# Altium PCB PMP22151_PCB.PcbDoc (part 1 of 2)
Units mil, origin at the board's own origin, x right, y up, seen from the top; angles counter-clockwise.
Board outline 3750 x 2000 mil, 2 copper layers (Top Layer, Bottom Layer), stack 62 mil thick; 80 components, 41 nets, 202 pads, 89 vias.
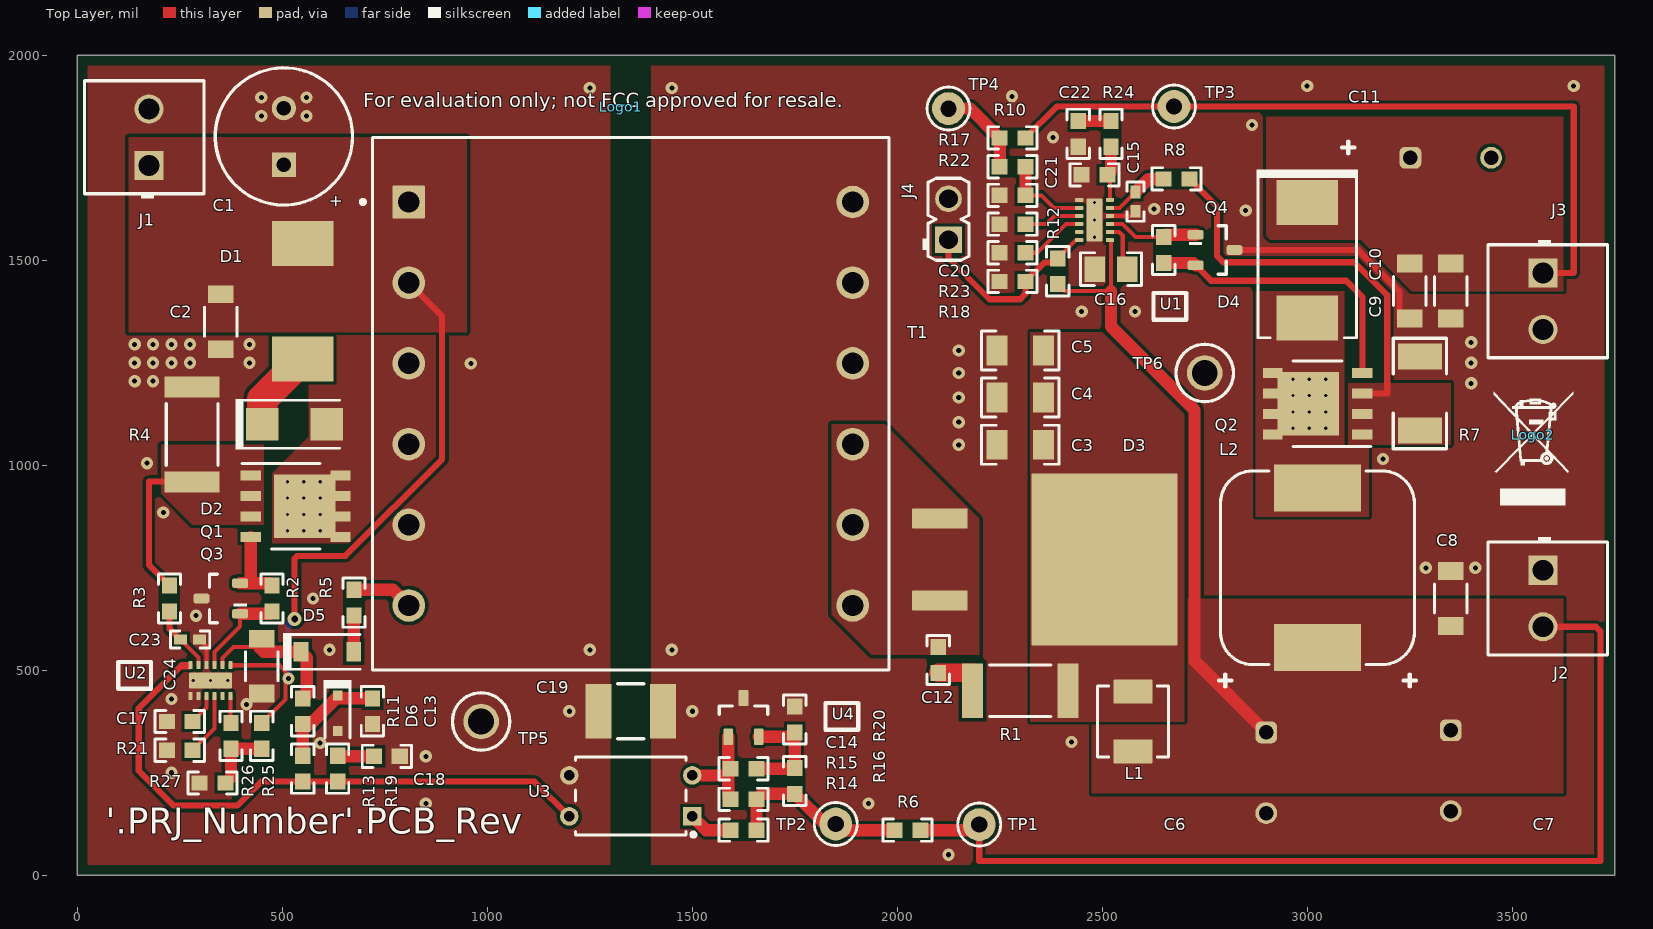
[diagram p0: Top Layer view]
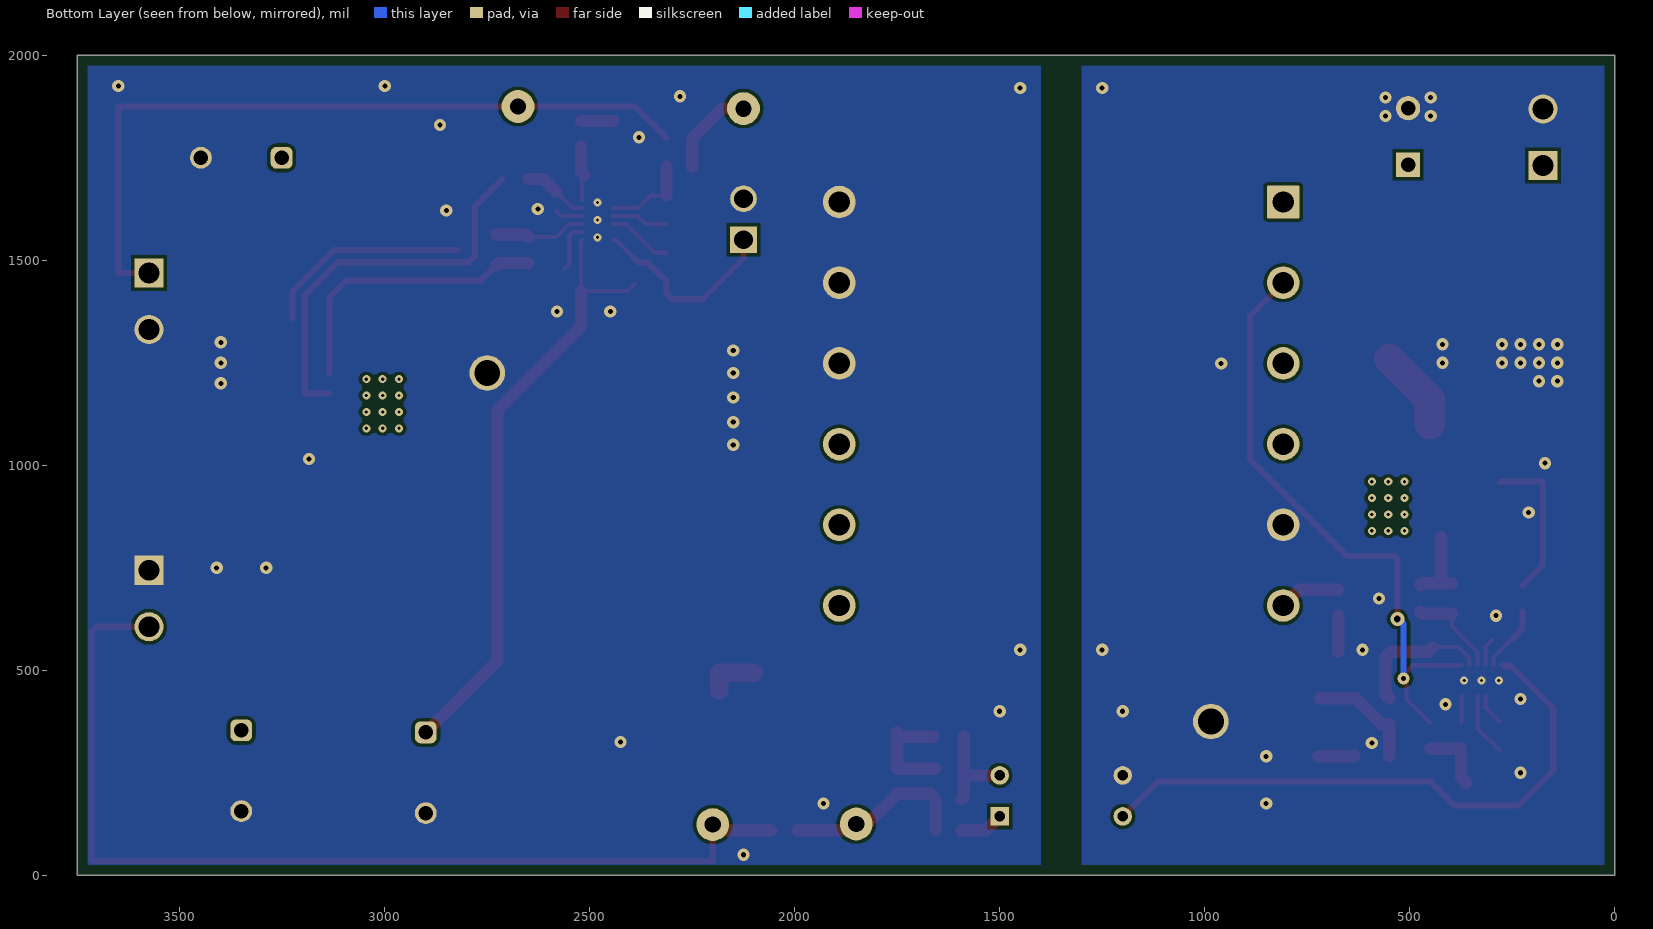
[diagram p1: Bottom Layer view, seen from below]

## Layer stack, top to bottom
Top Solder: solder mask 0.4, Solder Resist, Dk 3.5
Top Layer: signal copper 1.4
Dielectric1: core 59.2, FR-4, Dk 4.8
Bottom Layer: signal copper 1.4
Bottom Solder: solder mask 0.4, Solder Resist, Dk 3.5

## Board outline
0,0 3750,0 3750,2000 0,2000

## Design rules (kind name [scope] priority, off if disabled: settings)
AcuteAngle [All] p1: minimum=4.50000000000000E+0001 checktracksonly=FALSE
AssemblyTestPointUsage [All] p1: valid=2
BoardOutlineClearance BoardOutlineClearance_MountingHoles [OnCopper and InComponentClass('Mounting Holes')] p1: gap=25 ignorepadtopadclearanceinfootprint=FALSE
BoardOutlineClearance BoardOutlineClearance_Poly [OnCopper and InPoly] p2: gap=25 ignorepadtopadclearanceinfootprint=FALSE
BoardOutlineClearance [OnCopper and Not InComponentClass('Logo') and not InComponentClass('FiducialMark') and not InRegion(1000,500,4000,800)] p3: gap=25 ignorepadtopadclearanceinfootprint=FALSE
Clearance Clearance_Keepouts [((IsTrack Or IsArc) And Not InPoly) And IsFree and IsKeepOut vs ((IsTrack Or IsArc) And Not InPoly) And IsFree and IsKeepOut] p1: gap=0 ignorepadtopadclearanceinfootprint=FALSE
Clearance Clearance_Poly [InPolygon] p2: gap=8 ignorepadtopadclearanceinfootprint=FALSE except(0: Arc-Hole Track-Hole SMDPad-Hole THPad-Hole Via-Hole Fill-Hole Poly-Hole Region-Hole Text-Hole)
Clearance [All] p3: gap=7.87 ignorepadtopadclearanceinfootprint=FALSE except(0: Arc-Hole Track-Hole SMDPad-Hole THPad-Hole Via-Hole Fill-Hole Poly-Hole Region-Hole Text-Hole)
ComponentClearance ComponentClearance_MountingHoles_FiducialMarks [InComponentClass('Mounting Holes') vs InComponentClass('FiducialMark')] p1: gap=50 collisioncheckmode=3 verticalgap=10 showdistances=FALSE
ComponentClearance ComponentClearance_Shunt [InComponentClass('Header') vs InComponentClass('Shunt')] p2: gap=0 collisioncheckmode=3 verticalgap=0 showdistances=FALSE
ComponentClearance ComponentClearance_Logo [InComponentClass('Logo')] p3: gap=50 collisioncheckmode=3 verticalgap=10 showdistances=FALSE
ComponentClearance ComponentClearance_ScrewToNut [(HasFootprint('NY PMS 440 0025 PH')) vs (HasFootprint('Keystone_1902C'))] p4: gap=5 collisioncheckmode=3 verticalgap=10 showdistances=FALSE
ComponentClearance ComponentClearance_MountingHoles [InComponentClass('Mounting Holes')] p5: gap=250 collisioncheckmode=3 verticalgap=100000 showdistances=FALSE
ComponentClearance ComponentClearance_SmallPassives [HasFootprint('0201*') or HasFootprint('0402*') or HasFootprint('0508') or HasFootprint('0603*') or HasFootprint('0612') or HasFootprint('0805*') or HasFootprint('0815*') or HasFootprint('0830*') or HasFootprint('1206*') or HasFootprint('1210*') or HasFootprint('1808*') or HasFootprint('1812*') or HasFootprint('1825*') or HasFootprint('2010*') or HasFootprint('2220*') or HasFootprint('2225*') or HasFootprint('2512*') or HasFootprint('2728*') or HasFootprint('3518*') vs HasFootprint('0201*') or HasFootprint('0402*') or HasFootprint('0508') or HasFootprint('0603*') or HasFootprint('0612') or HasFootprint('0805*') or HasFootprint('0815*') or HasFootprint('0830*') or HasFootprint('1206*') or HasFootprint('1210*') or HasFootprint('1808*') or HasFootprint('1812*') or HasFootprint('1825*') or HasFootprint('2010*') or HasFootprint('2220*') or HasFootprint('2225*') or HasFootprint('2512*') or HasFootprint('2728*') or HasFootprint('3518*')] p6: gap=14.96 collisioncheckmode=3 verticalgap=10 showdistances=FALSE
ComponentClearance ComponentClearance_THtoSMT [IsThruComponent vs IsSMTComponent] p7: gap=15 collisioncheckmode=3 verticalgap=30 showdistances=FALSE
ComponentClearance ComponentClearance_THtoTH [IsThruComponent vs IsThruComponent] p8: gap=15 collisioncheckmode=3 verticalgap=30 showdistances=FALSE
ComponentClearance [All] p9: gap=15 collisioncheckmode=3 verticalgap=10 showdistances=FALSE
DiffPairsRouting [All] p1: maxlimit=100 minlimit=10 mostfreqgap=10 toplayer_minwidth=15 toplayer_maxwidth=15 toplayer_prefwidth=15 bottomlayer_minwidth=15 bottomlayer_maxwidth=15 bottomlayer_prefwidth=15 maxuncoupledlength=1000
FabricationTestPointUsage TestPointUsage [All] p1: valid=2 allowmultiple=FALSE
FabricationTestpoint Testpoint [All] p1: side=3 testpointundercomponent=TRUE minsize=40 maxsize=100 preferedsize=60 minholesize=0 maxholesize=40 preferedholesize=32 testpointgrid=1 allowsidetop=TRUE allowsidebottom=TRUE usegrid=TRUE gridtolerance=0.01
FanoutControl Fanout_LCC [IsLCC] p1: bgadir=Out bgaviamode=Centered fanoutstyle=Auto fanoutdirection=Alternating viagrid=1 // Fanout_LCC (Default Rule)
FanoutControl Fanout_BGA [IsBGA] p2: bgadir=Out bgaviamode=Centered fanoutstyle=Auto fanoutdirection=Alternating viagrid=1 // Fanout_BGA (Default Rule)
FanoutControl Fanout_Default [All] p4: bgadir=Out bgaviamode=Centered fanoutstyle=Auto fanoutdirection=Alternating viagrid=1 // Fanout_Default (Default Rule)
FanoutControl Fanout_Small [(CompPinCount < 5)] p5: bgadir=Out bgaviamode=Centered fanoutstyle=Auto fanoutdirection=OutThenIn viagrid=1 // Fanout_Small (Default Rule)
HoleSize [All] p1: absolutevalues=TRUE maxlimit=251 minlimit=7.87 maxpercent=80.000 minpercent=20.000
MinimumAnnularRing MinimumAnnularRing_ThermalPadVias [IsVia and InAnyComponent] p1: minimumring=5.91
MinimumAnnularRing [All] p2: minimumring=8
MinimumSolderMaskSliver MinimumSolderMaskSliver_Logo [InComponentClass('Logo') vs InComponentClass('Logo')] p1: minsoldermaskwidth=0.7
MinimumSolderMaskSliver [All] p2: minsoldermaskwidth=3.94
PlaneConnect [All] p1: planeconnectstyle=Direct reliefexpansion=10 reliefentries=4 reliefconductorwidth=10 reliefairgap=10
PolygonConnect [All] p1: connectstyle=Direct reliefconductorwidth=10 reliefentries=4 polygonreliefangle="90 Angle" airgapwidth=10
RoutingVias ThermalPadVias [IsVia and InAnyComponent] p1: holewidth=7.87 width=19.68 viastyle="Through Hole" minholewidth=7.87 minwidth=19.68 maxholewidth=12.99 maxwidth=23.62
RoutingVias [All] p2: holewidth=16 width=34 viastyle="Through Hole" minholewidth=7.87 minwidth=26 maxholewidth=40 maxwidth=65
SilkToBoardRegionClearance [Not ((IsComment or IsDesignator) And (Hide <> 'False')) and not InRegion(1000,500,4000,800)] p1:
SilkToSilkClearance SilkToSilkClearance_Pb-FreeLogo [(HasFootprint('Pb-Free_Overlay_Medium') OR HasFootprint('Pb-Free_Overlay_Small')) vs (HasFootprint('Pb-Free_Overlay_Medium') OR HasFootprint('Pb-Free_Overlay_Small'))] p1: silktosilkclearance=0
SilkToSilkClearance [All] p2: silktosilkclearance=4
SilkToSolderMaskClearance SilkToComponentPadClearance [IsPad and InAnycomponent] p1: minsilkscreentomaskgap=5 clearancetoexposedcopper=TRUE
SilkToSolderMaskClearance "Silk to Solder Mask Opening" [All] p2: minsilkscreentomaskgap=4 clearancetoexposedcopper=FALSE
SolderMaskExpansion [All] p1: expansion=1.97
Width [All] p1: maxlimit=100 minlimit=6 preferedwidth=10 checkconnectedcopper=TRUE
15 further rules are at their usual default settings.

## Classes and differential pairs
component class Header: J4

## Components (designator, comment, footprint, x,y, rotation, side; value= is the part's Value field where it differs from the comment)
C1 "50ZLJ100MT78X11.5" ZLJ_800X1150 504,1802 r90 top value=100uF
C2 "GRM31CR61H106KA12L" 1206_180 350,1350 r270 top value=10uF
C3 "GRM31MR71H105KA88L" 1206 2300,1050 r180 top value=1uF
C4 "GRM31MR71H105KA88L" 1206 2300,1165 r180 top value=1uF
C5 "GRM31MR71H105KA88L" 1206 2300,1280 r180 top value=1uF
C6 "860080675015" WCAP-ATLI_1000x1600 2900,250 r270 top value=220uF
C7 "860080675015" WCAP-ATLI_1000x1600 3350,255 r270 top value=220uF
C8 "GRM31CR71H475KA12L" 1206_180 3350,675 r90 top value=4.7uF
C9 "GRM31CR71H475KA12L" 1206_180 3350,1425 r270 top value=4.7uF
C10 "GRM31CR71H475KA12L" 1206_180 3250,1425 r270 top value=4.7uF
C11 "860080675015" WCAP-ATLI_1000x1600 3350,1750 r0 top value=220uF
C12 "GRM188R71H331KA01D" 0603 2100,525 r90 top value=330pF
C13 "GRM188R71E104KA01D" 0603 720,400 r90 top value=0.1uF
C14 "GRM188R71E153KA01D" 0603 1625,260 r180 top value=0.015uF
C15 "GRM1555C1E330JA01D" 0402 2581.3,1643.23 r270 top value=33pF
C16 "GRM219R71E105KA88D" 0805_HV 2521.3,1478.23 r180 top value=1uF
C17 "GRM188R71E104KA01D" 0603 250,375 r0 top value=0.1uF
C18 "GRM188R71E103KA01D" 0603 755,290 r180 top value=0.01uF
C19 "1812GC102KA1" 1812_254 1350,400 r180 top value=1000pF
C20 "GRM188R71E103KA01D" 0603 2281.3,1588.23 r180 top value=0.01uF
C21 "GRM188R71H821KA01D" 0603 2481.3,1708.23 r180 top value=820pF
C22 "GCM188R71E474KA64D" 0603 2441.3,1808.23 r270 top value=0.47uF
C23 "885012205055" 0402 275,575 r0 top value=100pF
C24 "C3216X7R1V106M160AC" 1206_190 450,510 r270 top value=10uF
D1 "SMCJ48CA-TR" SMC_Bi 550,1400 r270 top value=48V
D2 "MURA120T3G" SMA 530,1100 r0 top value=200V
D3 "MBRB20100CT-TP" DDPAK 2350,770 r0 top value=100V
D4 "B560C-13-F" SMC 3000,1500 r270 top value=60V
D5 "MMSD4148T1G" SOD-123 610,545 r0 top value=100V
D6 "MMSZ5231BS-7-F" SOD-323 635,395 r270 top value=5.1V
J1 "691214110002" Wurth_691214110002 175,1800 r90 top
J2 "691214110002" Wurth_691214110002 3575,675 r270 top
J3 "691214110002" Wurth_691214110002 3575,1400 r270 top
J4 "61300211121" WURTH_61300211121 2125,1600 r90 top
L1 "744373240010" WE-LHMI_4020 2575,375 r270 top value=100nH
L2 "7447709390" WE-PD_1210 3025,750 r90 top value=39uH
Logo1 "FCC disclaimer" FCC_disclaimer 1325,1875 r0 top
Logo2 "WEEE logo" WEEE_Minimum 3550,1075 r0 top
Q1 "SIR696DP-T1-GE3" PowerPAK_SO-8 532.5,900 r0 top value=200V
Q2 "SI7850DP-E3" PowerPAK_SO-8 3025,1150 r180 top value=60V
Q3 "MMBT3906" SOT-23 350,675 r180 top value="40 V"
Q4 "MMBT3906" SOT-23 2775,1525 r0 top value="40 V"
R1 "CRCW2512100RJNEG" 2512 2300,450 r0 top value=100
R2 "CRCW060310R0JNEA" 0603 475,675 r90 top value=10
R3 "CRCW06031K00FKEA" 0603 225,675 r90 top value=1.00k
R4 "ERJ-M1WSF8M0U" 2512 280,1075 r270 top value=0.008
R5 "CRCW060322R0JNEA" 0603 675,665 r90 top value=22
R6 "CRCW06030000Z0EA" 0603 2025,110 r0 top value=0
R7 "CSRN2010FK25L0" 2010 3275,1175 r270 top value=0.025
R8 "CRCW06031K00FKEA" 0603 2681.3,1698.23 r0 top value=1.00k
R9 "CRCW060310R0JNEA" 0603 2650,1525 r270 top value=10
R10 "CRCW06030000Z0EA" 0603 2281.3,1798.23 r0 top value=0
R11 "CRCW06032K49FKEA" 0603 550,400 r90 top value=2.49k
R12 "CRCW0603105KFKEA" 0603 2391.3,1473.23 r270 top value=105k
R13 "CRCW06032K49FKEA" 0603 550,260 r90 top value=2.49k
R14 "CRCW060310K0FKEA" 0603 1625,110 r0 top value=10.0k
R15 "CRCW060310K0FKEA" 0603 1625,185 r0 top value=10.0k
R16 "CRCW0603102KFKEA" 0603 1750,230 r270 top value=102k
R17 "CRCW0603100KFKEA" 0603 2281.3,1728.23 r180 top value=100k
R18 "CRCW060310K0FKEA" 0603 2281.3,1448.23 r0 top value=10.0k
R19 "CRCW0603499RFKEA" 0603 635,260 r270 top value=499
R20 "CRCW060310K0FKEA" 0603 1750,380 r270 top value=10.0k
R21 "CRCW0603215KFKEA" 0603 250,305 r180 top value=215k
R22 "CRCW06032K80FKEA" 0603 2281.3,1658.23 r0 top value=2.80k
R23 "CRCW060371K5FKEA" 0603 2281.3,1518.23 r0 top value=71.5k
R24 "CRCW060320K0FKEA" 0603 2521.3,1808.23 r270 top value=20.0k
R25 "CRCW0603105KFKEA" 0603 450,340 r90 top value=105k
R26 "CRCW060320K5FKEA" 0603 375,340 r90 top value=20.5k
R27 "CRCW060310K0FKEA" 0603 330,225 r0 top value=10.0k
T1 "750318773" FP-750318773_PTH_32MM0_33MM0-MFG 1350,1150 r0 top
TP1 "5000" Keystone5000 2200,123.74 r90 top
TP2 "5004" Keystone5004 1850,125 r90 top
TP3 "5000" Keystone5000 2675,1875 r90 top
TP4 "5004" Keystone5004 2125,1870 r90 top
TP5 "5011" Keystone5011 985,375 r0 top
TP6 "5011" Keystone5011 2750,1225 r0 top
U1 "LM5155DSST" DSS0012B 2481.3,1598.23 r180 top
U2 "LM5155DSST" DSS0012B 325,475 r270 top
U3 "VO618A-3" DIP-4 1350,193.43 r180 top
U4 "ATL431LIBIDBZR" DBZ0003A_N 1625,385 r90 top

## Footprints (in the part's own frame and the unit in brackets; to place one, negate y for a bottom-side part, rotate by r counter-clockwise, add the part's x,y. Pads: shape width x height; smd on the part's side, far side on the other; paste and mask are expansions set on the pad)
0402 [mm] "0402 from SM-752 data"
  rect 0.8x0.6 smd: 1(-0.6,0) 2(0.6,0)
  silkscreen extent -1.22,-0.52 1.22,0.52, body extent -0.55,-0.3 0.55,0.3, height 0.6
0603 [mm] "0603 from SM-752 data"
  rect 1x0.95 smd: 1(-0.8,0) 2(0.8,0)
  silkscreen extent -1.52,-0.69 1.52,0.69, body extent -0.87,-0.47 0.87,0.47, height 1
0805_HV [mil] "0805 with 30mil clearance between pads"
  rect 50x63 smd: 1(-40,0) 2(40,0)
  silkscreen extent -74,-40 74,40, body extent -43,-29 43,29, height 57
1206 [mm] "1206 from SM-752 data"
  rect 1.3x1.85 smd: 1(-1.45,0) 2(1.45,0)
  silkscreen extent -2.4,-1.21 2.4,1.21, body extent -1.7,-0.9 1.7,0.9, height 1.35
1206_180 [mm] "1206_180"
  rect 1.1x1.6 smd: 1(-1.7,0) 2(1.7,0)
  silkscreen extent -0.9,-1 0.9,1, body extent -1.75,-0.95 1.75,0.95, height 1.8
1206_190 [mm] "1206_190"
  rect 1.1x1.6 smd: 1(-1.7,0) 2(1.7,0)
  silkscreen extent -0.9,-1 0.9,1, body extent -1.75,-0.95 1.75,0.95, height 1.9
1812_254 [mm] "SMD, 2-Leads, Body 4.8x3.4mm"
  rect 1.6x3.4 smd: 1(-2,0) 2(2,0)
  silkscreen extent -0.8,-1.7 0.8,1.7, body extent -2.4,-1.7 2.4,1.7, height 2.54
2010 [mm] "Chip Capacitor, Body 5.08x2.54mm, IPC Medium Density"
  rect 1.6x2.7 smd: 1(-2.3,0) 2(2.3,0)
  silkscreen extent -3.42,-1.65 3.42,1.65, body extent -2.73,-1.45 2.73,1.45, height 1.66
2512 [mm] "Chip Resistor, Body 6.3x3.2mm, IPC Medium Density"
  rect 1.3x3.4 smd: 1(-2.95,0) 2(2.95,0)
  silkscreen extent -1.9,-1.6 1.9,1.6, body extent -3.22,-1.67 3.22,1.67, height 0.71
DBZ0003A_N [mm] "SOT23, 3-Leads, Body 2.9x1.3mm, Pitch 0.95mm, Lead Span 2.4mm, IPC Medium Density"
  rrect17% 1x0.6 smd: 1(-1.2,0.95) 2(-1.2,-0.95) 3(1.2,0)
  silkscreen extent 0.2,-1.5 0.7,1.5, body extent -1.26,-1.46 1.26,1.46, height 0.98
DDPAK [mil] "D2-PAK, 3-Pads, Body 9.7x10.4mm (max), TO-263AB, using Vishay Silionix recommended pad sizes"
  rrect8% 135x49.49 smd: 1(-246.06,100) 3(-246.06,-100)
  rrect1% 355x420 smd paste-181.1: 2(155.51,0)
  body extent -295,-202 324,202, height 180
DIP-4 [mm] "DIP, 4-Leads, Body 6.86x4.83mm, Pitch 2.54mm"
  rect 1.15x1.15 hole 0.65: 1(-3.81,1.27)
  round 1.15 hole 0.65: 2(-3.81,-1.27) 3(3.81,-1.27) 4(3.81,1.27)
  silkscreen extent -4,-2.41 3.43,2.52, body extent -4.02,-2.41 4.02,2.41, height 5.59
DSS0012B [mm] "WSON-10"
  rrect40% 0.5x0.25 smd: 1(-0.95,1.25) 2(-0.95,0.75) 3(-0.95,0.25) 4(-0.95,-0.25) 5(-0.95,-0.75) 6(-0.95,-1.25) 7(0.95,-1.25) 8(0.95,-0.75) 9(0.95,-0.25) 10(0.95,0.25) 11(0.95,0.75) 12(0.95,1.25)
  rrect11% 1x2.65 smd paste-0.5: 13(0,0)
  body extent -1,-1.5 1,1.5, height 0.81
FCC_disclaimer [mil]
FP-750318773_PTH_32MM0_33MM0-MFG [mm]
  rrect5% 2.02x2.02 hole 1.32 paste-1000 mask+0: 1(-13.75,12.5)
  round 2.02 hole 1.32 paste-1000 mask+0: 2(-13.75,7.5) 3(-13.75,2.5) 4(-13.75,-2.5) 5(-13.75,-7.5) 6(-13.75,-12.5) 7(13.75,-12.5) 8(13.75,-7.5) 9(13.75,-2.5) 10(13.75,2.5) 11(13.75,7.5) 12(13.75,12.5)
  silkscreen extent -16.72,-16.5 16,16.5, body extent -16.1,-16.6 16.1,16.6, height 0.25
Keystone5000 [mil] "For Keystone 500x miniature loop terminals"
  round 80 hole 40: 1(0,0)
  silkscreen extent -52,-52 52,52, body extent -49,-49 49,49, height 182
Keystone5004 [mil] "For Keystone 500x miniature loop terminals"
  round 80 hole 40: 1(0,0)
  silkscreen extent -52,-52 52,52, body extent -49,-49 49,49, height 182
Keystone5011 [mil] "Keystone Multipurpose loops"
  round 87 hole 63: 1(0,0)
  silkscreen extent -70,-70 70,70, body extent -63,-63 63,62, height 319
PowerPAK_SO-8 [mil] "Vishay PowerPAK SO-8, Body 5.3x6.0mm (max), Pitch 1.27mm, IPC Medium Density"
  rect 50x24 smd mask+2.99: 1(-109.5,75) 2(-109.5,25) 3(-109.5,-25) 4(-109.5,-75)
  rect 48x24 smd mask+2.99: 5(109.5,-75) 8(109.5,75)
  rect 48x24 smd paste-12 mask+2.99: 6(109.5,-25) 7(109.5,25)
  rect 150x154 smd paste-75 mask+2.99: 9(22.5,0)
  silkscreen extent -130,-104 59,104, body extent -121,-102 121,102, height 43
SMA [mm] "Molded Diode, 2-Leads, Body 4.3x2.6mm, IPC Medium Density, based on OnSemi component dimensions and land pattern"
  rect 2x2 smd: 1(-2,0) 2(2,0)
  silkscreen extent -3.66,-1.57 2.79,1.57, body extent -2.6,-1.3 2.6,1.3, height 2.42
SMC [mil] "Molded Diode, 2-Leads, Body 6.9x5.8mm, IPC Medium Density, based on OnSemi component dimensions and land patterns"
  rect 110x150 smd: 1(-140.49,0) 2(140.49,0)
  silkscreen extent -221,-123 189,124, body extent -156,-116 156,116, height 91
SMC_Bi [mil] "SMC, no polarity mark"
  rect 110x150 smd: 1(-140.49,0) 2(140.49,0)
  body extent -156,-116 156,116, height 92
SOD-123 [mm] "On Semi recommended land pattern"
  rect 0.915x1.22 smd: 1(-1.637,0) 2(1.637,0)
  silkscreen extent -2.74,-1.17 2.03,1.17, body extent -1.93,-0.9 1.93,0.9, height 1.35
SOD-323 [mm] "NXP recommended land pattern"
  rect 0.6x0.6 smd paste-0.05: 1(-1.1,0) 2(1.1,0)
  silkscreen extent -2.06,-0.86 1.53,0.86, body extent -1.3,-0.67 1.3,0.68, height 1.1
SOT-23 [mm] "SOT23, 3-Leads, Body 2.9x1.3mm, Pitch 0.95mm, Lead Span 2.5mm, IPC Medium Density"
  rrect50% 1x0.6 smd: 1(-1.2,0.95) 2(-1.2,-0.95) 3(1.2,0)
  silkscreen extent -1.62,-1.5 0.7,1.5, body extent -1.16,-1.45 1.21,1.45, height 1
WCAP-ATLI_1000x1600 [mm] "TH, 2-Leads, Dia 10mm, Pin Spacing 5mm"
  rrect50% 1.35x1.35 hole 0.9: 1(-2.5,0)
  round 1.35 hole 0.9: 2(2.5,0)
  body extent -5.25,-5.25 5.26,5.25, height 17.51
WE-LHMI_4020 [mm] "WERTH"
  rrect7% 1.5x2.4 smd: 1(-1.85,0) 2(1.85,0)
  silkscreen extent -2.2,-2.2 2.2,2.2, body extent -2.15,-2.15 2.15,2.15, height 2
WE-PD_1210 [mm] "Wurth Elektronik recommended land pattern"
  rect 2.9x5.4 smd: 1(-4.95,0) 2(4.95,0)
  silkscreen extent -6,-6 6,6, body extent -6,-6 6,6, height 10.01
WEEE_Minimum [mil] "WEEElie bin"
  silkscreen extent -95,-172 99,104
WURTH_61300211121 [mm] "Header, 2.54mm, 2x1, TH"
  rect 1.65x1.65 hole 1.15: 1(-1.27,0)
  round 1.65 hole 1.15: 2(1.27,0)
  silkscreen extent -2.54,-1.27 2.54,1.6, body extent -2.54,-1.27 2.54,1.27, height 8.54
Wurth_691214110002 [mm] "Receptacle, 3.5mm, 2x1, TH"
  rect 1.8x1.8 hole 1.3: 1(-1.75,0)
  round 1.8 hole 1.3: 2(1.75,0)
  silkscreen extent -3.8,-3.4 3.5,4, body extent -3.9,-3.4 3.5,4, height 8.5
ZLJ_800X1150 [mm] "Rubycon"
  rect 1.5x1.5 hole 0.889: 1(-1.75,0)
  round 1.5 hole 0.889: 2(1.75,0)
  silkscreen extent -4.25,-4.25 4.25,4.25, body extent -4.22,-4.24 4.24,4.24, height 13.01

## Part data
C1: library part CMP-0009787-2, "CAP, AL, 100 uF, 50 V, +/- 20%, 0.12 ohm, TH", Cap_Case=8x11.5, Manufacturer=Rubycon, Supplier Part Number 1=1189-1662-1-ND, Tolerance_%=20%, Value1="0.12 ohm", Value2=50V, ValueDisplayed=100uF
C2: library part CMP-0008954-2, "CAP, CERM, 10 uF, 50 V, +/- 10%, X5R, 1206", Cap_Case=1206, Manufacturer=MuRata, Supplier Part Number 1=490-5961-1-ND, TempCo=X5R, Tolerance_%=10%, Value1=Unknown, Value2=50V, ValueDisplayed=10uF
C3 C4 C5: library part CMP-0008992-2, "CAP, CERM, 1 uF, 50 V, +/- 10%, X7R, 1206", Cap_Case=1206, Manufacturer=MuRata, Supplier Part Number 1=GRM31MR71H105KA88L-ND, TempCo=X7R, Tolerance_%=10%, Value1=Unknown, Value2=50V, ValueDisplayed=1uF
C6 C7 C11: library part CMP-0081643-1, "CAP, AL, 220 µF, 50 V, +/- 20%, TH", Cap_Case=10x16mm, Manufacturer="Wurth Elektronik", Supplier Part Number 1=732-9057-1-ND, Tolerance_%=20%, Value2=50V, ValueDisplayed=220µF
C8 C9 C10: library part CMP-0008969-2, "CAP, CERM, 4.7 uF, 50 V, +/- 10%, X7R, 1206", Cap_Case=2220, Manufacturer=MuRata, Supplier Part Number 1=24R6347, TempCo=X7R, Tolerance_%=10%, Value1=Unknown, Value2=50V, ValueDisplayed=4.7uF
C12: library part CMP-0007449-4, "CAP, CERM, 330 pF, 50 V, +/- 10%, X7R, 0603", Cap_Case=0603, Manufacturer=MuRata, Supplier Part Number 1=490-1486-1-ND, TempCo=X7R, Tolerance_%=10%, Value1=Unknown, Value2=50V, ValueDisplayed=330pF
C13 C17: library part CMP-0007404-4, "CAP, CERM, 0.1 uF, 25 V, +/- 10%, X7R, 0603", Cap_Case=0603, Manufacturer=MuRata, Supplier Part Number 1=490-1524-1-ND, TempCo=X7R, Tolerance_%=10%, Value1=Unknown, Value2=25V, ValueDisplayed=0.1uF
C14: library part CMP-0007410-5, "CAP, CERM, 0.015 uF, 25 V, +/- 10%, X7R, 0603", Cap_Case=0603, Manufacturer=MuRata, Supplier Part Number 1=81-GRM39X153K25D, TempCo=X7R, Tolerance_%=10%, Value1=Unknown, Value2=25V, ValueDisplayed=0.015uF
C15: library part CMP-0006377-2, "CAP, CERM, 33 pF, 25 V, +/- 5%, C0G/NP0, 0402", Cap_Case=0402, Manufacturer=MuRata, Supplier Part Number 1=81-GRM1555C1E330JA1D, TempCo=C0G/NP0, Tolerance_%=5%, Value1=Unknown, Value2=25V, ValueDisplayed=33pF
C16: library part CMP-0008217-2, "CAP, CERM, 1 uF, 25 V, +/- 10%, X7R, 0805", Cap_Case=0805, Manufacturer=MuRata, Supplier Part Number 1=GRM219R71E105KA88D-ND, TempCo=X7R, Tolerance_%=10%, Value1=Unknown, Value2=25V, ValueDisplayed=1uF
C18 C20: library part CMP-0007403-4, "CAP, CERM, 0.01 uF, 25 V, +/- 10%, X7R, 0603", Cap_Case=0603, Manufacturer=MuRata, Supplier Part Number 1=490-1520-1-ND, TempCo=X7R, Tolerance_%=10%, Value1=Unknown, Value2=25V, ValueDisplayed=0.01uF
C19: library part CMP-0009293-2, "CAP, CERM, 1000 pF, 2000 V, +/- 10%, X7R, 1812", Cap_Case=1812, Manufacturer=AVX, Supplier Part Number 1=581-1812GC102KA11A, TempCo=X7R, Tolerance_%=10%, Value1=Unknown, Value2=2000V, ValueDisplayed=1000pF
C21: library part CMP-0007464-4, "CAP, CERM, 820 pF, 50 V, +/- 10%, X7R, 0603", Cap_Case=0603, Manufacturer=MuRata, Supplier Part Number 1=490-1493-1-ND, TempCo=X7R, Tolerance_%=10%, Value1=Unknown, Value2=50V, ValueDisplayed=820pF
C22: library part CMP-0007142-4, "CAP, CERM, 0.47 uF, 25 V, +/- 10%, X7R, AEC-Q200 Grade 1, 0603", Cap_Case=0603, Manufacturer=MuRata, Supplier Part Number 1=490-4776-1-ND, TempCo=X7R, Tolerance_%=10%, Value1=Unknown, Value2=25V, ValueDisplayed=0.47uF
C23: library part CMP-0006230-2, "CAP, CERM, 100 pF, 50 V, +/- 10%, X7R, 0402", Cap_Case=0402, Manufacturer="Wurth Elektronik", Supplier Part Number 1=732-7550-1-ND, TempCo=X7R, Tolerance_%=10%, Value1=Unknown, Value2=50V, ValueDisplayed=100pF
C24: library part CMP-0008706-2, "CAP, CERM, 10 uF, 35 V, +/- 20%, X7R, 1206_190", Cap_Case=1206, Manufacturer=TDK, Supplier Part Number 1=445-8034-1-ND, TempCo=X7R, Tolerance_%=20%, Value1=Unknown, Value2=35V, ValueDisplayed=10uF
D1: library part CMP-0085460-1, "Diode, TVS, Bi, 48 V, 77.4 Vc, 1500 W, 20 A, SMC (No Polarity Mark)", Manufacturer=STMicroelectronics, Value1=77.4V
D2: library part CMP-0029038-2, "Diode, Ultrafast, 200 V, 1 A, SMA", Manufacturer="ON Semiconductor", Value1=1A, Value2=0.0875V
D3: library part CMP-0076915-3, "Diode, Schottky, 100 V, 20 A, DDPAK", Manufacturer="Micro Commercial Components", Value1=20A, Value2=0.85V
D4: library part CMP-0028433-2, "Diode, Schottky, 60 V, 5 A, SMC", Manufacturer="Diodes Inc.", Value1=5A, Value2=0.7V
D5: library part CMP-0029032-2, "Diode, Switching, 100 V, 0.2 A, SOD-123", Manufacturer="ON Semiconductor", Value1=0.2A, Value2=1V
D6: library part CMP-0005854-3, "Diode, Zener, 5.1 V, 200 mW, SOD-323", Manufacturer="Diodes Inc.", Power_W=200mW, Value1=0.2W
J1 J2 J3: library part CMP-0054825-2, "Terminal Block, 3.5mm, 2x1, Tin, TH", Color=Green, Current_A=10A, Manufacturer="Wurth Elektronik", Supplier Part Number 1=732-2747-ND, Voltage_V=300V
J4: library part CMP-0054794-1, "Header, 2.54 mm, 2x1, Gold, TH", Manufacturer="Wurth Elektronik", Supplier Part Number 1=732-5315-ND
L1: library part CMP-0064065-1, "Inductor, Shielded Drum Core, Powdered Iron, 100 nH, 12 A, 0.0032 ohm, SMD", Manufacturer="Wurth Elektronik", Supplier Part Number 1=732-3344-1-ND, Value1="0.0032 ohm", Value2=12A, ValueDisplayed=100nH
L2: library part CMP-0064541-2, "Inductor, Shielded Drum Core, Metal Composite, 39 uH, 4.1 A, 0.0439 ohm, SMD", Manufacturer="Wurth Elektronik", Supplier Part Number 1=732-1245-1-ND, Value1="0.0439 ohm", Value2=4.1A, ValueDisplayed=39uH
Logo1: library part CMP-0074847-1, "FCC_disclaimer"
Logo2: library part CMP-0074769-1
Q1: library part CMP-0086346-1, "MOSFET, N-CH, 150V, 60 A, PowerPAK SO-8", Alternate Manufacturer=None, Manufacturer=Vishay-Siliconix, Value1="? ohm", Value2="? nC"
Q2: library part CMP-0000869-1, "MOSFET, N-CH, 60 V, 6.2 A, PowerPAK SO-8", Alternate Manufacturer=None, Manufacturer=Vishay-Siliconix, Supplier Part Number 1=SI7850DP-T1-E3CT-ND, Value1=0.02, Value2="18 nC"
Q3 Q4: library part CMP-0000325-1, "Transistor, PNP, 40 V, 0.2 A, SOT-23", Manufacturer="Fairchild Semiconductor", Supplier Part Number 1=MMBT3906FSCT-ND, Value1="0.2 A", Value2=300
R1: library part CMP-0015867-3, "RES, 100, 5%, 1 W, AEC-Q200 Grade 0, 2512", Manufacturer=Vishay-Dale, Power_W=1W, Supplier Part Number 1=541-100XCT-ND, TempCo="200 ppm/C", Tolerance_%=5%, Value_Code=100R, ValueDisplayed=100
R2 R9: library part CMP-0025703-4, "RES, 10, 5%, 0.1 W, AEC-Q200 Grade 0, 0603", Manufacturer=Vishay-Dale, Power_W=100mW, Supplier Part Number 1=541-10GCT-ND, TempCo="200 ppm/C", Tolerance_%=5%, Value2=0.1W, Value_Code=10R0, ValueDisplayed=10
R3 R8: library part CMP-0022109-5, "RES, 1.00 k, 1%, 0.1 W, AEC-Q200 Grade 0, 0603", Manufacturer=Vishay-Dale, Power_W=100mW, Supplier Part Number 1=541-1.00KHCT-ND, TempCo="100 ppm/C", Tolerance_%=1%, Value2=0.1W, Value_Code=1k00, ValueDisplayed=1.00k
R4: library part CMP-0015816-2, "RES, 0.008, 1%, 1 W, 2512", Manufacturer=Panasonic, Power_W=1W, Supplier Part Number 1=P8.0MCT-ND, TempCo="100 ppm/C", Tolerance_%=1%, Value_Code=8L000, ValueDisplayed=0.008
R5: library part CMP-0025758-4, "RES, 22, 5%, 0.1 W, AEC-Q200 Grade 0, 0603", Manufacturer=Vishay-Dale, Power_W=100mW, Supplier Part Number 1=541-22GCT-ND, TempCo="200 ppm/C", Tolerance_%=5%, Value2=0.1W, Value_Code=22R0, ValueDisplayed=22
R6 R10: library part CMP-0025697-4, "RES, 0, 5%, 0.1 W, AEC-Q200 Grade 0, 0603", Manufacturer=Vishay-Dale, Power_W=100mW, Supplier Part Number 1=541-0.0GCT-ND, TempCo="200 ppm/C", Tolerance_%=5%, Value2=0.1W, Value_Code=0000, ValueDisplayed=0
R7: library part CMP-0016517-2, "RES, 0.025, 1%, 1 W, 2010", Manufacturer="Stackpole Electronics Inc", Power_W=1W, Supplier Part Number 1=CSRN2010FK25L0CT-ND, TempCo="250 ppm/C", Tolerance_%=1%, Value_Code=R025, ValueDisplayed=0.025
R11 R13: library part CMP-0022277-4, "RES, 2.49 k, 1%, 0.1 W, AEC-Q200 Grade 0, 0603", Manufacturer=Vishay-Dale, Power_W=100mW, Supplier Part Number 1=541-2.49KHCT-ND, TempCo="100 ppm/C", Tolerance_%=1%, Value2=0.1W, Value_Code=2k49, ValueDisplayed=2.49k
R12 R25: library part CMP-0021994-4, "RES, 105 k, 1%, 0.1 W, AEC-Q200 Grade 0, 0603", Manufacturer=Vishay-Dale, Power_W=100mW, Supplier Part Number 1=541-105KHCT-ND, TempCo="100 ppm/C", Tolerance_%=1%, Value2=0.1W, Value_Code=105k
R14 R15 R18 R20 R27: library part CMP-0021998-4, "RES, 10.0 k, 1%, 0.1 W, AEC-Q200 Grade 0, 0603", Manufacturer=Vishay-Dale, Power_W=100mW, Supplier Part Number 1=541-10.0KHCT-ND, TempCo="100 ppm/C", Tolerance_%=1%, Value2=0.1W, Value_Code=10k0, ValueDisplayed=10.0k
R16: library part CMP-0021992-4, "RES, 102 k, 1%, 0.1 W, AEC-Q200 Grade 0, 0603", Manufacturer=Vishay-Dale, Power_W=100mW, Supplier Part Number 1=541-102KHCT-ND, TempCo="100 ppm/C", Tolerance_%=1%, Value2=0.1W, Value_Code=102k
R17: library part CMP-0021990-4, "RES, 100 k, 1%, 0.1 W, AEC-Q200 Grade 0, 0603", Manufacturer=Vishay-Dale, Power_W=100mW, Supplier Part Number 1=541-100KHCT-ND, TempCo="100 ppm/C", Tolerance_%=1%, Value2=0.1W, Value_Code=100k
R19: library part CMP-0022446-5, "RES, 499, 1%, 0.1 W, AEC-Q200 Grade 0, 0603", Manufacturer=Vishay-Dale, Power_W=100mW, Supplier Part Number 1=541-499HCT-ND, TempCo="100 ppm/C", Tolerance_%=1%, Value2=0.1W, Value_Code=499R, ValueDisplayed=499
R21: library part CMP-0022210-4, "RES, 215 k, 1%, 0.1 W, AEC-Q200 Grade 0, 0603", Manufacturer=Vishay-Dale, Power_W=100mW, Supplier Part Number 1=541-215KHCT-ND, TempCo="100 ppm/C", Tolerance_%=1%, Value2=0.1W, Value_Code=215k
R22: library part CMP-0022282-4, "RES, 2.80 k, 1%, 0.1 W, AEC-Q200 Grade 0, 0603", Manufacturer=Vishay-Dale, Power_W=100mW, Supplier Part Number 1=541-2.80KHCT-ND, TempCo="100 ppm/C", Tolerance_%=1%, Value2=0.1W, Value_Code=2k80, ValueDisplayed=2.80k
R23: library part CMP-0022581-4, "RES, 71.5 k, 1%, 0.1 W, AEC-Q200 Grade 0, 0603", Manufacturer=Vishay-Dale, Power_W=100mW, Supplier Part Number 1=541-71.5KHCT-ND, TempCo="100 ppm/C", Tolerance_%=1%, Value2=0.1W, Value_Code=71k5, ValueDisplayed=71.5k
R24: library part CMP-0022204-4, "RES, 20.0 k, 1%, 0.1 W, AEC-Q200 Grade 0, 0603", Manufacturer=Vishay-Dale, Power_W=100mW, Supplier Part Number 1=541-20.0KHCT-ND, TempCo="100 ppm/C", Tolerance_%=1%, Value2=0.1W, Value_Code=20k0, ValueDisplayed=20.0k
R26: library part CMP-0022205-4, "RES, 20.5 k, 1%, 0.1 W, AEC-Q200 Grade 0, 0603", Manufacturer=Vishay-Dale, Power_W=100mW, Supplier Part Number 1=541-20.5KHCT-ND, TempCo="100 ppm/C", Tolerance_%=1%, Value2=0.1W, Value_Code=20k5, ValueDisplayed=20.5k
